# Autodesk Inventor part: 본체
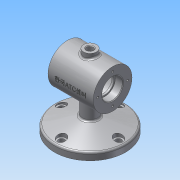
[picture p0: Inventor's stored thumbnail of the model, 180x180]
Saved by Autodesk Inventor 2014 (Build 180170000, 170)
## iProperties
Created: 2018-12
Part Number: 본체
Material: 알루미늄 6061
Document SubType Name: Modeling
Designer: sda
Mass: 688.56 g
Surface Area: 557.83 cm^2
Volume: 254.081 cm^3
Density: 2.71 g/cm^3
Appearance: 알루미늄 - 평지
Author: sda
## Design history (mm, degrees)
sketch "스케치1"
  geometry: C1 r 55 at (0, 0); 1 further point
  constraints: 1 centre point, 1 coincident
  dimensions: "d0" = 110 diameter of C1
extrude "돌출1" new body sketch "스케치1" distance "d1" = 11; taper "d2" = 0 deg
node "작업 평면1"
sketch "스케치2"
  geometry: L1 (55, 11)-(-55, 11) reference; L2 (55, 11)-(0, 25.737); L3 (0, 25.737)-(0, 11); L4 (55, 0)-(55, 11) reference; 1 further point
  constraints: 4 end point, 1 midpoint, 1 vertical
  dimensions: "d5" = 75 deg angle of L4 L2
revolve "회전1" sketch "스케치2" stored, may be unused: angle "d6" = 90 deg
node "작업 평면2"
node "작업 평면3"
node "작업 평면5"
sketch "스케치6"
  geometry: L1 (0, 0)-(35, 0); L2 (0, 0)-(-35, 0); L3 (-35, 0)-(-35, -30); L4 (-35, -30)-(35, -30); L5 (35, -30)-(35, 0); C1 r 55 at (0, 0) reference; 2 further points
  constraints: 10 end point, 2 perpendicular, 1 collinear, 1 horizontal, 1 parallel
  dimensions: "d38" = 35 distance of L1.start L1.end; "d39" = 35 distance of L1.start L2.end; "d40" = 30 distance of L2.end L3.end
revolve "회전4" sketch "스케치6" stored, may be unused: angle "d41" = 90 deg
sketch "스케치7"
  geometry: L1 (0, 25.737)-(55, 11) reference; L2 (55, 11)-(55, 0) reference; L3 (55, 0)-(-55, 0) reference; L4 (-55, 0)-(-55, 11) reference; L5 (-55, 11)-(0, 25.737) reference; L6 (-35, 45)-(-35, 105) reference; L7 (-35, 105)-(35, 105) reference; L8 (35, 105)-(35, 45) reference; L9 (35, 45)-(-35, 45) reference; L10 (55, 11)-(55, 0) reference; L11 (55, 0)-(-55, 0) reference; L12 (-55, 0)-(-55, 11) reference; L13 (-35, 45)-(-35, 105) reference; L14 (-35, 105)-(35, 105) reference; L15 (35, 105)-(35, 45) reference; L16 (35, 45)-(-35, 45) reference; L17 (-35, 75)-(35, 75); L18 (-35, 91)-(-23, 91); L19 (-23, 91)-(-23, 89); L20 (-23, 89)-(-20, 89); L21 (-20, 89)-(-20, 100); L22 (-20, 100)-(20, 100); L23 (20, 100)-(20, 89); L24 (20, 89)-(23, 89); L25 (23, 89)-(23, 91); L26 (23, 91)-(35, 91); L27 (0, 25.737)-(55, 11) reference; L28 (-55, 11)-(0, 25.737) reference; 1 further point
  constraints: 20 end point, 7 parallel, 2 midpoint, 2 perpendicular, 2 point on line
  dimensions: "d42" = 50 diameter of L22 L17; "d44" = 28 diameter of L20 L17; "d45" = 28 diameter of L24 L17; "d46" = 32 diameter of L26 L17; "d47" = 32 diameter of L18 L17; "d48" = 3 distance between parallel lines of L21 L19; "d49" = 3 distance between parallel lines of L25 L23; "d50" = 40 distance between parallel lines of L23 L21; "d51" = 12 distance between parallel lines of L19 L6
revolve "회전5" sketch "스케치7" stored, may be unused: angle "d52" = 90 deg
chamfer "모따기3" distance "d53" = 1; stored, may be unused: second distance "d54" = 2, angle "d55" = 45 deg
chamfer "모따기4" distance "d56" = 1; stored, may be unused: second distance "d57" = 2, angle "d58" = 45 deg
fillet "모깎기3" dims "d59" = 0.3
fillet "모깎기4" dims "d60" = 3
sketch "스케치8"
  geometry: L1 (35, 45)-(35, 105) reference; L2 (-35, 45)-(-35, 105) reference; L3 (-35, 45)-(35, 45) reference; L4 (0, 25.737)-(55, 11) reference; L5 (0, 45)-(0, 25.737); L6 (12, 45)-(12, 22.522); 1 further point
  constraints: 4 end point, 2 point on line, 1 midpoint, 1 parallel, 1 perpendicular
  dimensions: "d61" = 12 distance between parallel lines of L6 L5
revolve "회전6" sketch "스케치8" stored, may be unused: angle "d62" = 90 deg
sketch "스케치9"
  geometry: A1 r 12 centre (0, 0) between (12, 0) and (-12, 0) reference; 1 further point
  constraints: 1 coincident, 1 horizontal alignment, 2 other
extrude "돌출2" join sketch "스케치9" stored distance "d63" = 10; taper "d64" = 0 deg
node "작업 평면6"
sketch "스케치10"
  geometry: C1 r 10 at (0, 0); 1 further point
  constraints: 1 centre point, 1 coincident
  dimensions: "d66" = 20 diameter of C1
extrude "돌출3" join sketch "스케치10" stored distance "d67" = 10; taper "d68" = 0 deg
hole "구멍1" diameter "d71" = 10; stored, may be unused: countersink angle "d75" = 90 deg, drill point angle "d77" = 118 deg; dims "d69" = 10, "d70" = 10, "d72" = 6, "d73" = 4, "d74" = 2, "d76" = 8
chamfer "모따기5" distance "d78" = 1; stored, may be unused: second distance "d79" = 2, angle "d80" = 45 deg
sketch "스케치11" dims "d81" = 46
  geometry: C1 r 17 at (0, 0) reference; 3 further points
  constraints: 2 vertical alignment, 1 coincident, 2 other
hole "구멍2" sketch "스케치11" at (0, 23) diameter "d82" = 3.242; stored, may be unused: countersink angle "d86" = 90 deg, drill point angle "d88" = 118 deg; dims "d83" = 8, "d84" = 4, "d85" = 2, "d87" = 10
sketch "스케치12" dims "d92" = 88
  geometry: C1 r 55 at (0, 0) reference; 2 further points
  constraints: 2 vertical alignment, 1 coincident, 2 other
hole "구멍3" sketch "스케치12" at (0, 44) diameter "d93" = 9; stored, may be unused: countersink angle "d97" = 90 deg, drill point angle "d99" = 118 deg; dims "d94" = 8, "d95" = 4, "d96" = 2, "d98" = 10
node "작업 평면7"
sketch "스케치13"
  geometry: C1 r 4.5 at (0, 44) reference; C2 r 55 at (0, 0) reference; C3 r 7 at (0, 44); 1 further point
  constraints: 1 centre point, 1 coincident
  dimensions: "d101" = 14 diameter of C3
extrude "돌출4" cut sketch "스케치13" distance "d102" = 10; taper "d103" = 0 deg
fillet "모깎기5" dims "d107" = 3
node "작업 평면8"
sketch "스케치14"
  geometry: L1 (-35, -30)-(-35, 30) reference; L2 (35, -30)-(35, 30) reference; L3 (-24.887, 3.602)-(24.887, 3.602); L4 (24.887, 3.602)-(24.887, -3.602); L5 (24.887, -3.602)-(-24.887, -3.602); L6 (-24.887, -3.602)-(-24.887, 3.602); L7 (0, 3.602)-(0, -3.602); L8 (-24.887, 0)-(24.887, 0); L9 (-35, 30)-(35, 30) reference; 2 further points
  constraints: 4 end point, 4 midpoint, 1 vertical alignment, 2 other
  dimensions: "d108" = 30 distance between parallel lines of L8 L9
feature "엠보싱1" sketch "스케치14" dims "d2" = 0, "d38" = 35, "d39" = 35, "d40" = 30, "d109" = 0.5, "d110" = 0
fillet "모깎기6" dims "d111" = 3
node "솔리드1"
pattern_circular "원형 패턴1" dims angle "d90" = 360 deg
mirror "대칭1"
pattern_circular "원형 패턴2" dims angle "d105" = 360 deg
node "투영된 루프1"
node "투영된 루프2"
node "절단 모서리 투영2"
node "절단 모서리 투영3"
node "절단 모서리 투영4"
other parameters: "d3" = 0, "d7" = -75, "d11" = 0, "d35" = -75, "d65" = -112
